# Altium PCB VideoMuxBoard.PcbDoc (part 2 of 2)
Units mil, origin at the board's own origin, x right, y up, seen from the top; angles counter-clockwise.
Board outline 4724.41 x 4724.41 mil, 4 copper layers (Top Layer, Ground, MidLayer1, Bottom Layer); 247 components, 183 nets, 999 pads, 433 vias.
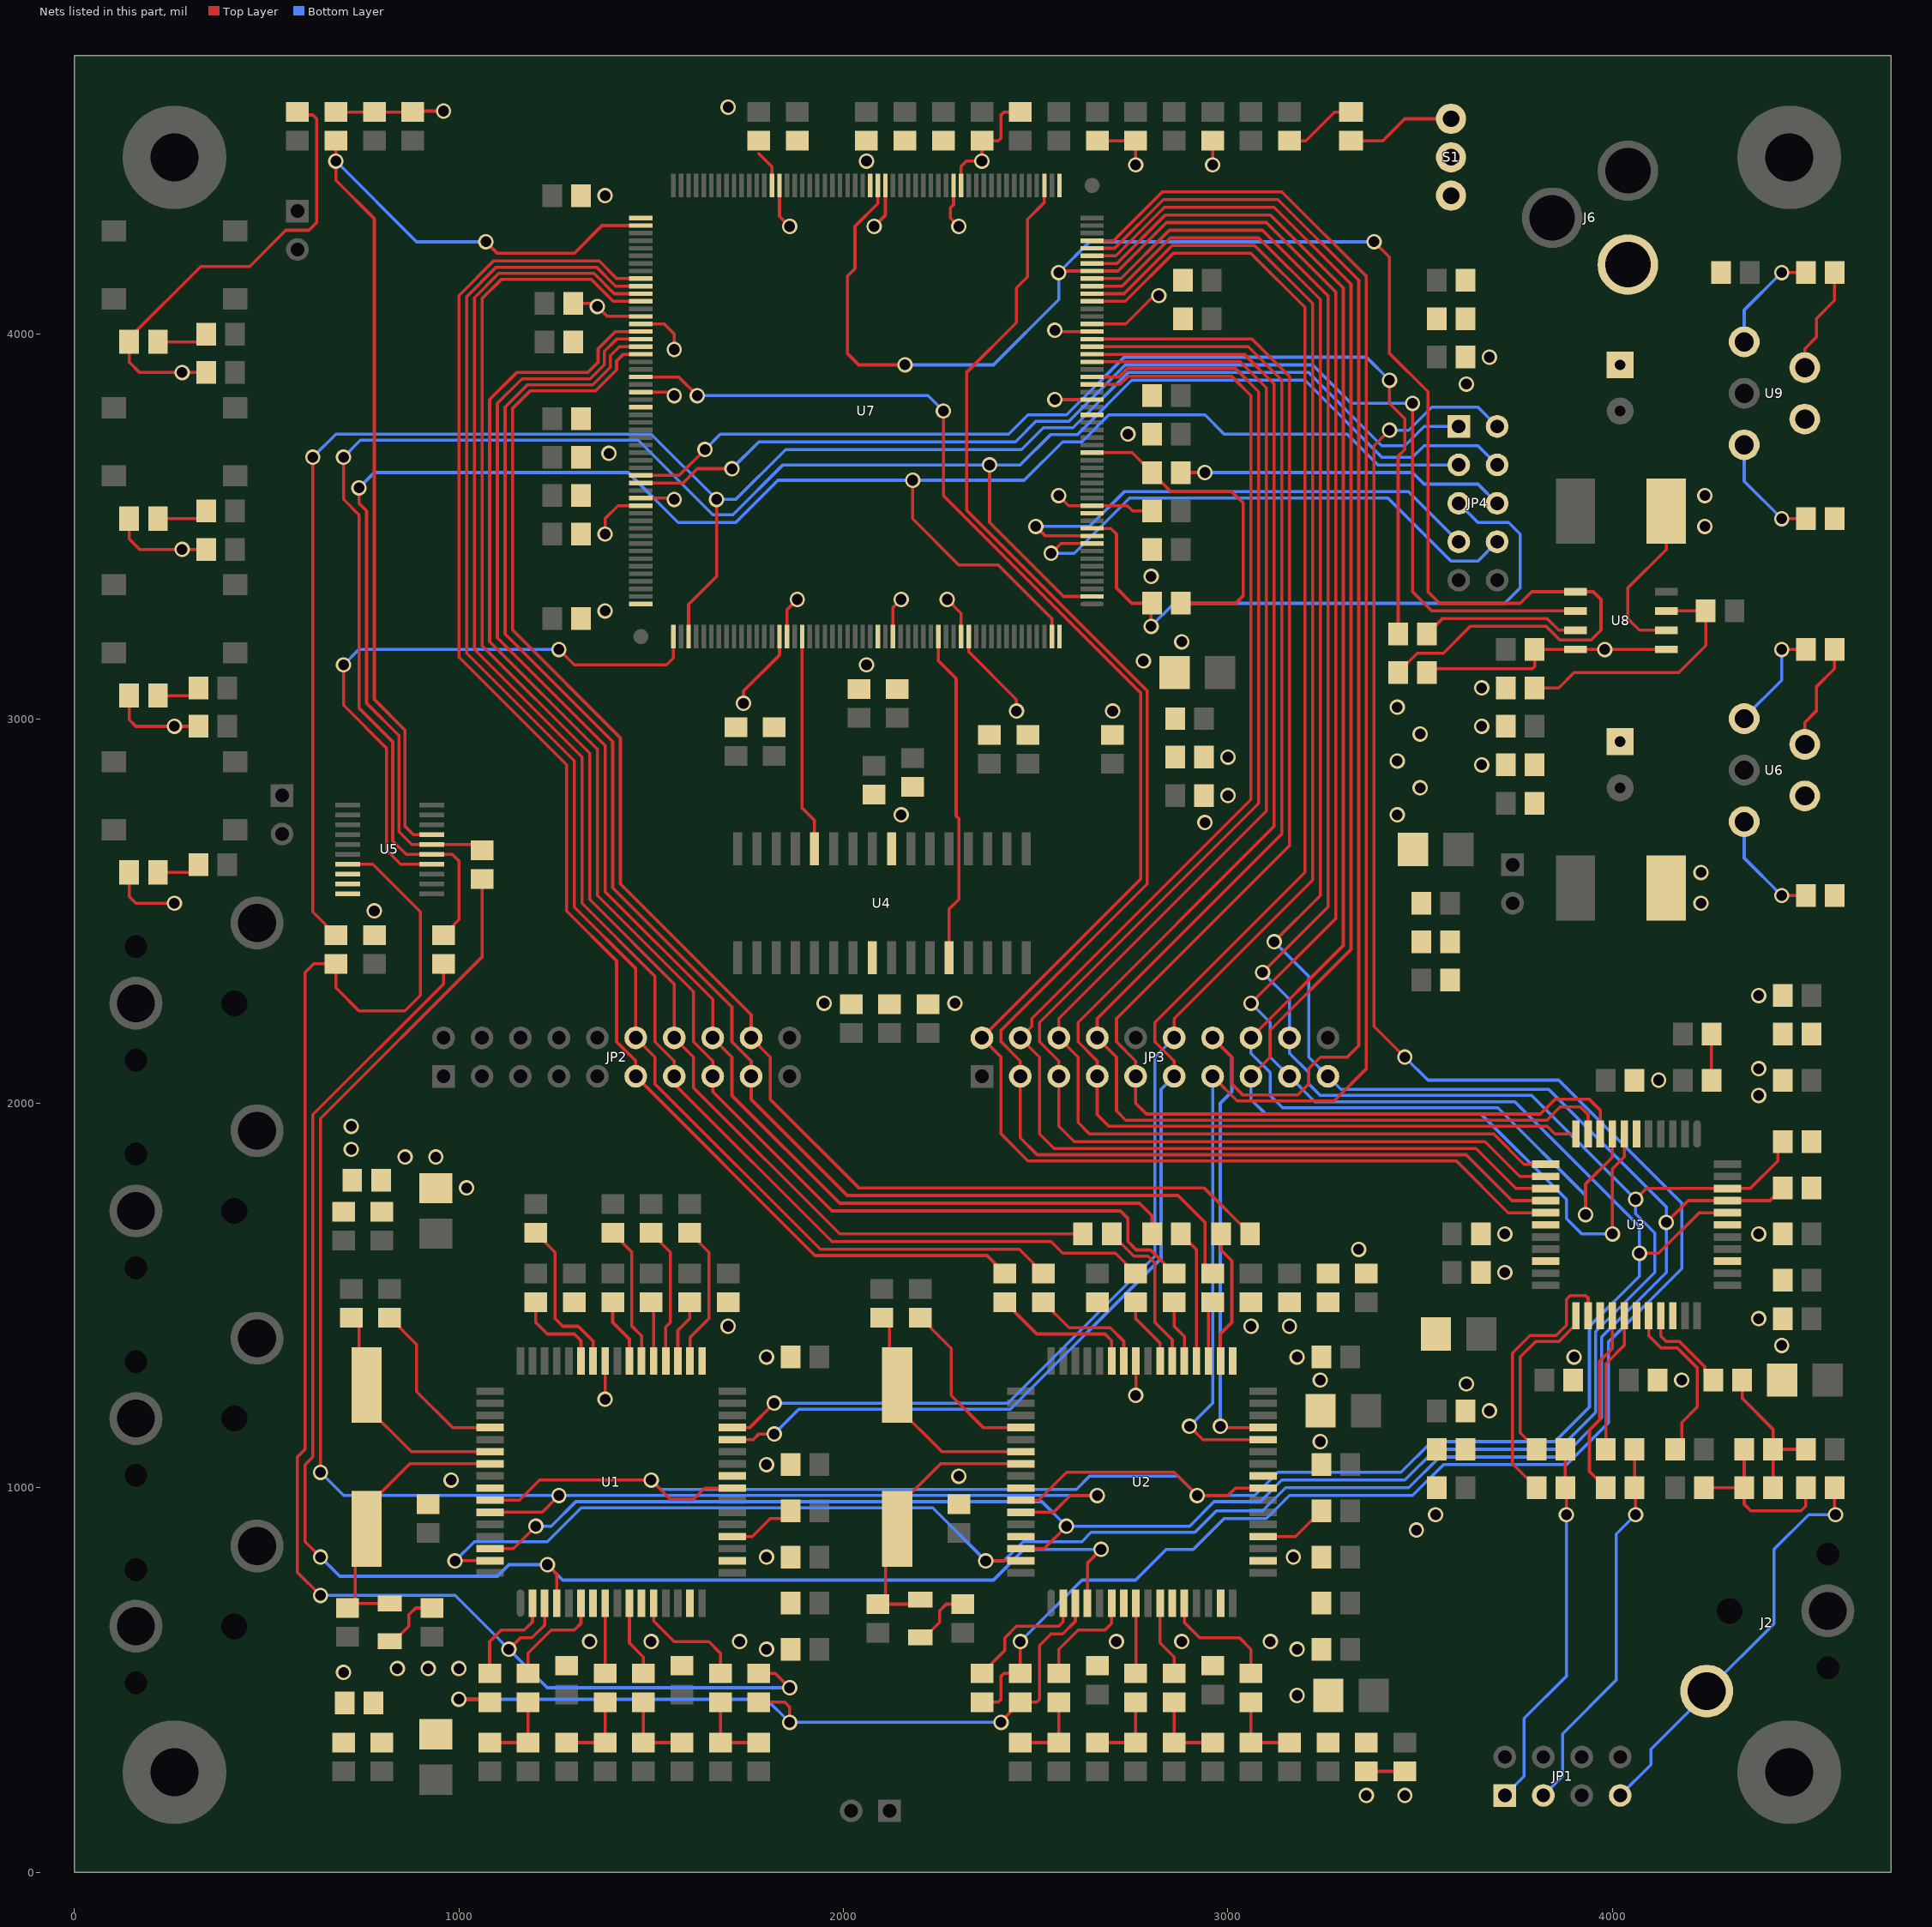
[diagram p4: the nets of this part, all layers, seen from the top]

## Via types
v1: diameter 40, hole 28, Top Layer to Bottom Layer, 433 vias

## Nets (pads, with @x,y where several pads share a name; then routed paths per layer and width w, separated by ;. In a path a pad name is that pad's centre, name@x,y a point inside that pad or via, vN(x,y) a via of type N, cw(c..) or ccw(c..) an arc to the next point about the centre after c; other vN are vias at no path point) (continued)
MPB0: JP2.11 R35.1 U7.113 | length 3922.4
  Top Layer w8: U7.113@1473.36,4144.46 1410,4144.46 1364.46,4190 1090,4190 1000,4100 1000,3160 1280,2880 1280,2500 1410,2370 1410,2160 1460,2110 JP2.11@1460,2070 1926,1604 2373.4,1604 R35.1@2420,1557.4
MPB1: JP2.12 R36.1 U7.114 | length 3969.9
  Top Layer w8: U7.114@1473.36,4124.78 1407.06,4124.78 1357.84,4174 1096.63,4174 1020,4097.37 1020,3170 1300,2890 1300,2510 1460,2350 JP2.12@1460,2170 1510,2120 1510,2050 1940,1620 2457.4,1620 R36.1@2520,1557.4
MPB2: JP2.13 R37.1 U7.115 | length 4150.9
  Top Layer w8: U7.115@1473.36,4105.09 1404.12,4105.09 1351.21,4158 1103.25,4158 1040,4094.75 1040,3180 1320,2900 1320,2520 1510,2330 1510,2160 1560,2110 JP2.13@1560,2070 ; JP2.13@1565.25,2070 JP2.13@1560,2070 ; R37.1@2760,1557.4 2707.4,1610 2570,1610 2540,1640 1970,1640 1560,2050 JP2.13@1560,2070
MPB3: JP2.14 R44.1 U7.116 | length 3907.4
  Top Layer w8: U7.116@1473.36,4085.41 1401.17,4085.41 1344.58,4142 1109.88,4142 1060,4092.12 1060,3190 1340,2910 1340,2530 1560,2310 JP2.14@1560,2170 1610,2120 1610,2040 1990,1660 R44.1@2622.6,1660
MPB4: JP2.15 R38.1 U7.120 | length 3958
  Top Layer w8: U7.120@1473.36,4006.67 1406.67,4006.67 1362,3962 1362,3927.25 1334.75,3900 1150,3900 1080,3830 1080,3200 1360,2920 1360,2540 1610,2290 1610,2160 1660,2110 JP2.15@1660,2070 1660,2030 1970,1720 2720,1720 2740,1700 2740,1640.03 2761.56,1618.47 2798.93,1618.47 R38.1@2860,1557.4
MPB5: JP2.16 R45.1 U7.121 | length 3784.8
  Top Layer w8: U7.121@1473.36,3986.98 1410,3986.98 1378,3954.98 1378,3920.63 1341.37,3884 1164,3884 1100,3820 1100,3210 1380,2930 1380,2550 1660,2270 JP2.16@1660,2170 1710,2120 1710,2020 1990,1740 2770,1740 2802.6,1707.4 R45.1@2802.6,1660
MPB6: JP2.17 R39.1 U7.122 | length 3954.6
  Top Layer w8: U7.122@1473.36,3967.3 1417.3,3967.3 1394,3944 1394,3914 1348,3868 1178,3868 1120,3810 1120,3220 1400,2940 1400,2560 1710,2250 1710,2160 1760,2110 JP2.17@1760,2070 1760,2010 2010,1760 2870,1760 2940,1690 2940,1577.4 R39.1@2960,1557.4
MPB7: JP2.18 R46.1 U7.123 | length 3872.4
  Top Layer w8: 1354.63,3853.44 1354.63,3852 1184.63,3852 1140,3807.37 1140,3230 1420,2950 1420,2570 1760,2230 JP2.18@1760,2170 1810,2120 1810,2010 2040,1780 2937.4,1780 R46.1@3057.4,1660 ; 1355.35,3852.72 1410,3907.37 1410,3930 1427.61,3947.61 U7.123@1473.36,3947.61
MPOUT0: JP3.2 U3.16 U7.126 | length 4609.1
  Top Layer w8: U7.126@1473.36,3888.56 1571.44,3888.56 v1(1620,3840) ; v1(2260,3800) 2260,3580 2773.5,3066.5 2773.5,2583.5 JP3.2@2360,2170 2410,2120 2410,1920 2480,1850 3594.14,1850 3728.87,1715.28 U3.16@3826.3,1715.27
  Bottom Layer w8: v1(1620,3840) 2220,3840 v1(2260,3800)
MPOUT1: JP3.3 U3.15 U7.55 | length 4367.2
  Top Layer w8: U7.55@2522.57,4386.59 2522.58,4342.58 2478.76,4298.76 2478.76,4148.76 2450,4120 2450,4030 2320,3900 2320,3542.63 2790,3072.63 2790,2570 2410,2190 2410,2160 2460,2110 JP3.3@2460,2070 2460,1910 2504,1866 3619.64,1866 3738.87,1746.77 U3.15@3826.3,1746.77
MPOUT2: JP3.4 U3.14 U7.30 | length 4007.1
  Top Layer w8: U7.30@2646.59,3868.87 2718.87,3868.87 2740,3890 3010,3890 3060,3840 3060,2790 2490,2220 2490,2200 JP3.4@2460,2170 2510,2120 2510,1920 2548,1882 3645.14,1882 3748.87,1778.27 U3.14@3826.3,1778.27
MPOUT3: JP3.5 U3.13 U7.31 | length 3954.2
  Top Layer w8: U7.31@2646.59,3888.56 2715.93,3888.56 2737.37,3910 3020,3910 3080,3850 3080,2780 2510,2210 2510,2160 2560,2110 JP3.5@2560,2070 2560,1940 2600,1900 3668.63,1900 3758.87,1809.76 U3.13@3826.3,1809.76
MPOUT4: JP3.6 U3.12 U7.33 | length 3897.3
  Top Layer w8: U7.33@2646.59,3927.93 3032.07,3927.93 3100,3860 3100,2760 2560,2220 JP3.6@2560,2170 2610,2120 2610,1950 2640,1920 3691.26,1920 3770,1841.26 U3.12@3826.3,1841.26
MPOUT5: JP3.7 U3.11 U7.34 | length 3903.3
  Top Layer w8: U7.34@2646.59,3947.61 3042.39,3947.61 3120,3870 3120,2720 2610,2210 2610,2160 2660,2110 JP3.7@2660,2070 2660,1970 2690,1940 3830,1940 3850,1920 U3.11@3905.04,1920
MPOUT6: JP3.8 U3.10 U7.35 | length 3957.9
  Top Layer w8: U7.35@2646.59,3967.3 3052.7,3967.3 3140,3880 3140,2700 2660,2220 JP3.8@2660,2170 2710,2120 2710,1980 2734,1956 3829.48,1956 3863.48,1990 3916.54,1990 3936.54,1970 U3.10@3936.53,1920
MPOUT7: JP3.9 U3.9 U7.36 | length 3959.6
  Top Layer w8: U7.36@2646.59,3986.98 3063.02,3986.98 3160,3890 3160,2670 2710,2220 2710,2160 2760,2110 JP3.9@2760,2070 2760,2000 2788,1972 3812,1972 3850,2010 3940,2010 3968.03,1981.97 U3.9@3968.03,1920
NetC3_1: C3.1 R9.2 R11.2 | length 205.2
  Top Layer w8: R9.2@2460,337.4 R11.2@2560,337.4 C3.1@2560,442.6
NetC3_2: C3.2 U2.6 | length 280.5
  Top Layer w8: C3.2@2560,517.4 2560,580 2610,630 2680,630 2697.48,647.48 U2.6@2697.48,700
NetC5_1: C5.1 R12.2 R13.2 | length 205.2
  Top Layer w8: R12.2@2660,337.4 R13.2@2760,337.4 C5.1@2760,442.6
NetC5_2: C5.2 U2.8 | length 182.8
  Top Layer w8: C5.2@2760,517.4 2760.47,517.88 U2.8@2760.47,700
NetC6_1: C6.1 R14.2 R15.2 | length 205.2
  Top Layer w8: C6.1@2860,442.6 R14.2@2860,337.4 R15.2@2960,337.4
NetC6_2: C6.2 U2.10 | length 197.7
  Top Layer w8: U2.10@2823.47,700 2823.46,596.54 2860,560 C6.2@2860,517.4
NetC8_1: C8.1 R16.2 R17.2 | length 205.2
  Top Layer w8: C8.1@3060,442.6 R16.2@3060,337.4 R17.2@3160,337.4
NetC8_2: C8.2 U2.12 | length 315.1
  Top Layer w8: U2.12@2886.46,700 2886.46,650 2926.46,610 3030,610 3060,580 C8.2@3060,517.4
NetC12_1: C12.1 R1.2 R2.2 | length 205.2
  Top Layer w8: R1.2@1080,337.4 R2.2@1180,337.4 C12.1@1180,442.6
NetC12_2: C12.2 U1.6 | length 274.7
  Top Layer w8: C12.2@1180,517.4 1180,570 1240,630 1300,630 1317.48,647.48 U1.6@1317.48,700
NetC14_1: C14.1 R3.2 R4.2 | length 205.2
  Top Layer w8: R3.2@1280,337.4 R4.2@1380,337.4 C14.1@1380,442.6
NetC14_2: C14.2 U1.8 | length 182.1
  Top Layer w8: C14.2@1380.47,517.88 U1.8@1380.47,700
NetC15_1: C15.1 R5.2 R6.2 | length 205.2
  Top Layer w8: C15.1@1480,442.6 R5.2@1480,337.4 R6.2@1580,337.4
NetC15_2: C15.2 U1.10 | length 197.7
  Top Layer w8: U1.10@1443.47,700 1443.46,596.54 1480,560 C15.2@1480,517.4
NetC17_1: C17.1 R7.2 R8.2 | length 205.2
  Top Layer w8: C17.1@1680,442.6 R7.2@1680,337.4 R8.2@1780,337.4
NetC17_2: C17.2 U1.12 | length 307.2
  Top Layer w8: U1.12@1506.46,700 1506.46,653.54 1560,600 1650,600 1680,570 C17.2@1680,517.4
NetC20_2: C20.2 L4.2 U2.55 X2.1 | length 755.9
  Top Layer w8: L4.2@2200,709.21 2188.19,697.4 C20.2@2090,697.4 2110,717.4 2110,862.99 X2.1@2140,892.99 2140,950 2252.2,1062.2 U2.55@2461.26,1062.2
NetC21_2: C21.2 L4.1 | length 163.5
  Top Layer w8: L4.1@2200,610.79 2210.79,610.79 2250,650 2250,680 2267.4,697.4 C21.2@2310,697.4
NetC22_2: C22.2 L3.2 U1.55 X1.1 | length 749.2
  Top Layer w8: C22.2@710,687.4 C22.2@721.81,699.21 ; L3.2@820,699.21 C22.2@721.81,699.21 ; U1.55@1081.26,1062.2 872.2,1062.2 760,950 X1.1@760,892.99 730,862.99 730,707.4 C22.2@721.81,699.21
NetC23_2: C23.2 L3.1 | length 163.5
  Top Layer w8: L3.1@820,600.79 830.79,600.79 870,640 870,670 887.4,687.4 C23.2@930,687.4
NetC33_1: C33.1 C34.2 L5.1 L7.2 | length 467.6
  Top Layer w8: C33.1@4237.4,1000 C34.2@4342.6,1000 ; L7.2@4342.6,1100 C34.2@4342.6,1000 ; L5.1@4502.6,1000 4502.6,952.6 4490,940 4360,940 4342.6,957.4 C34.2@4342.6,1000
NetC42_1: C42.1 U1.54 X1.2 | length 618.6
  Top Layer w8: C42.1@720,1442.6 740,1422.6 740,1287.01 X1.2@760,1267.01 760,1210 876.3,1093.7 U1.54@1081.26,1093.7
NetC49_1: C49.1 U2.54 X2.2 | length 618.6
  Top Layer w8: C49.1@2100,1442.6 2120,1422.6 2120,1287.01 X2.2@2140,1267.01 2140,1210 2256.3,1093.7 U2.54@2461.26,1093.7
NetC67_1: C67.1 R49.2 | length 120
  Top Layer w8: R49.2@4257.4,2060 C67.1@4257.4,2180
NetC79_1: C79.1 C80.1 L13.2 R60.2 U6.2 | length 279
  Top Layer w8: U6.2@4500,2933.07 4500,2990 4530,3020 4530,3082.6 4577.4,3130 R60.2@4577.4,3180
NetC96_1: C96.1 C106.1 L14.2 R69.2 U9.2 | length 279
  Top Layer w8: U9.2@4500,3913.07 4500,3962 4530,3992 4530,4040 4577.4,4087.4 R69.2@4577.4,4160
NetJ2_1: J2.1 JP1.7 L5.2 | length 1070.4
  Top Layer w8: v1@4577.4,932.6 L5.2@4577.4,1000
  Bottom Layer w8: JP1.7@4020,200 4100,280 4100,320 4245.04,465.04 J2.1@4245.04,471.34 4420,646.3 4420,840 4510,930 v1(4580,930)
NetJP4_6: JP4.6 R66.2 | length 855.7
  Top Layer w8: R66.2@2877.4,3640 v1(2940,3640)
  Bottom Layer w8: v1(2940,3640) 3480,3640 3510,3610 3650,3610 JP4.6@3700,3560
NetLED1_2: LED1.2 R53.1 | length 113.5
  Top Layer w8: LED1.2@217.4,2600 302.6,2600 R53.1@322.6,2620
NetLED2_2: LED2.2 R56.1 | length 113.5
  Top Layer w8: LED2.2@217.4,3060 302.6,3060 R56.1@322.6,3080
NetLED3_2: LED3.2 R65.1 | length 133.5
  Top Layer w8: LED3.2@217.4,3520 322.6,3520 R65.1@342.6,3540
NetLED4_2: LED4.2 R68.1 | length 133.5
  Top Layer w8: LED4.2@217.4,3980 322.6,3980 R68.1@342.6,4000
NetLED5_2: LED5.2 R77.1 | length 191
  Top Layer w8: R77.1@3160,4502.6 3202.6,4502.6 3277.4,4577.4 LED5.2@3320,4577.4
NetR18_2: R19.2 U2.2 | length 334.6
  Top Layer w8: R19.2@2360,517.4 2420,577.4 2420,610 2450,640 2560,640 2571.5,651.5 U2.2@2571.5,700
NetR19_2: R18.2 U1.2 | length 263.9
  Top Layer w8: R18.2@1080,517.4 1080,600 1110,630 1170,630 1191.5,651.5 U1.2@1191.5,700
NetR21_2: R21.2 U1.20 | length 179.1
  Top Layer w8: U1.20@1711.18,873.23 1763.23,873.23 1810,920 1842.6,920 R21.2@1862.6,940
NetR22_2: R22.2 U2.20 | length 179.1
  Top Layer w8: U2.20@3091.18,873.23 3175.83,873.23 R22.2@3242.6,940
NetR23_1: R23.1 U3.24 | length 722.8
  Top Layer w8: R23.1@3802.6,1000 3740,1062.6 3740,1350 3785.87,1395.87 3853.42,1395.87 3880,1422.45 3880,1490 3890,1500 3930,1500 3936.53,1493.47 U3.24@3936.53,1447.56
NetR24_1: R24.1 U3.26 | length 489.9
  Top Layer w8: R24.1@3982.6,1000 3940,1042.6 3940,1150 3966.72,1176.72 3966.72,1329.17 3999.53,1361.98 U3.26@3999.53,1447.56
NetR25_1: R25.1 U3.23 | length 460.4
  Top Layer w8: R25.1@3802.6,1100 3760,1142.6 3760,1340 3800,1380 3860,1380 3905.04,1425.04 U3.23@3905.04,1447.56
NetR26_1: R26.1 U3.27 | length 367.6
  Top Layer w8: R26.1@3982.6,1100 3982.6,1322.6 4031.02,1371.02 U3.27@4031.02,1447.56
NetR27_1: R27.1 U3.29 | length 448.4
  Top Layer w8: U3.29@4094.02,1447.56 4094.02,1395.98 4125.87,1364.13 4168.32,1364.13 4220,1312.45 4220,1210 4180,1170 4180,1117.4 R27.1@4162.6,1100
NetR28_1: R28.1 U3.30 | length 244.8
  Top Layer w8: U3.30@4125.51,1447.56 4125.51,1394.49 4140,1380 4174.9,1380 4240,1314.9 4240,1302.6 R28.1@4262.6,1280
NetR29_2: R29.2 U1.52 | length 451.5
  Top Layer w8: R29.2@820,1442.6 890,1372.6 890,1250 983.31,1156.69 U1.52@1081.26,1156.69
NetR30_2: R30.2 U1.43 | length 242.3
  Top Layer w8: R30.2@1200,1482.6 1200,1430 1230,1400 1300,1400 1317.48,1382.52 U1.43@1317.48,1329.92
NetR31_2: R31.2 U1.39 | length 170.7
  Top Layer w8: R31.2@1400,1482.6 1400,1430 1443.46,1386.54 U1.39@1443.47,1329.92
NetR32_2: R32.2 U1.37 | length 155.4
  Top Layer w8: R32.2@1500,1482.6 1506.46,1476.14 U1.37@1506.46,1329.92
NetR33_2: R33.2 U1.35 | length 165.3
  Top Layer w8: U1.35@1569.45,1329.92 1569.45,1409.45 1600,1440 R33.2@1600,1482.6
NetR34_2: R34.2 U2.52 | length 451.5
  Top Layer w8: R34.2@2200,1442.6 2280,1362.6 2280,1240 2363.31,1156.69 U2.52@2461.26,1156.69
NetR35_2: R35.2 U2.43 | length 371.5
  Top Layer w8: R35.2@2420,1482.6 2502.6,1400 2680,1400 2697.48,1382.52 U2.43@2697.48,1329.92
NetR36_2: R36.2 U2.42 | length 302.2
  Top Layer w8: R36.2@2520,1482.6 2586.6,1416 2694,1416 2728.98,1381.02 U2.42@2728.98,1329.92
NetR37_2: R37.2 U2.39 | length 179
  Top Layer w8: R37.2@2760,1482.6 2760,1440 2823.46,1376.54 U2.39@2823.47,1329.92
NetR38_2: R38.2 U2.37 | length 163.6
  Top Layer w8: R38.2@2860,1482.6 2860,1420 2886.46,1393.54 U2.37@2886.46,1329.92
NetR39_2: R39.2 U2.35 | length 157
  Top Layer w8: U2.35@2949.45,1329.92 2949.45,1472.05 R39.2@2960,1482.6
NetR40_2: R40.2 U1.42 | length 417.8
  Top Layer w8: R40.2@1200,1662.6 1250,1612.6 1250,1440 1270,1420 1310,1420 1348.98,1381.02 U1.42@1348.98,1329.92
NetR41_2: R41.2 U1.38 | length 363.7
  Top Layer w8: R41.2@1400,1662.6 1450,1612.6 1450,1420 1474.96,1395.04 U1.38@1474.96,1329.92
NetR42_2: R42.2 U1.36 | length 358.4
  Top Layer w8: R42.2@1500,1662.6 1550,1612.6 1550,1430 1537.95,1417.95 U1.36@1537.95,1329.92
NetR43_2: R43.2 U1.34 | length 373.7
  Top Layer w8: R43.2@1600,1662.6 1650,1612.6 1650,1440 1600.95,1390.94 U1.34@1600.95,1329.92
NetR44_2: R44.2 U2.38 | length 417.2
  Top Layer w8: R44.2@2697.4,1660 2754.93,1602.47 2792.3,1602.47 2810,1584.77 2810,1430 2854.96,1385.04 U2.38@2854.96,1329.92
NetR45_2: R45.2 U2.36 | length 346.9
  Top Layer w8: R45.2@2877.4,1660 2917.95,1619.45 U2.36@2917.95,1329.92
NetR46_2: R46.2 U2.34 | length 353.5
  Top Layer w8: U2.34@2980.94,1329.92 2980.94,1400.94 3010,1430 3010,1590 2982.6,1617.4 R46.2@2982.6,1660
NetR52_1: R52.1 U6.5 | length 295.3
  Top Layer w8: v1(4440,2540) R52.1@4502.6,2540
  Bottom Layer w8: U6.5@4342.52,2732.28 4342.52,2637.48 v1(4440,2540)
NetR58_2: R58.2 R62.1 U8.3 | length 683.4
  Top Layer w8: R58.2@3797.4,3080 3860,3080 3900,3120 4172.6,3120 4242.6,3190 R62.1@4242.6,3280 U8.3@4140,3280
NetR59_2: R59.2 U8.7 | length 415.4
  Top Layer w8: R59.2@3517.4,3220 3557.4,3260 3830,3260 3860,3230 U8.7@3903.78,3230
NetR60_1: R60.1 U6.1 | length 286.5
  Top Layer w8: v1(4440,3180) R60.1@4502.6,3180
  Bottom Layer w8: U6.1@4340,3000 4341.26,3001.26 U6.1@4342.52,3002.52 ; U6.1@4342.52,3000 U6.1@4342.52,3002.52 ; v1(4440,3180) 4440,3100 U6.1@4342.52,3002.52
NetR64_1: R64.1 U9.5 | length 295.3
  Top Layer w8: v1(4440,3520) R64.1@4502.6,3520
  Bottom Layer w8: U9.5@4342.52,3712.28 4342.52,3617.48 v1(4440,3520)
NetR69_1: R69.1 U9.1 | length 283
  Top Layer w8: v1(4440,4160) R69.1@4502.6,4160
  Bottom Layer w8: U9.1@4342.52,3980 4342.52,4062.52 v1(4440,4160)
OEBAR: U4.28 U7.174 | length 565
  Top Layer w8: U7.174@1892.65,3213.36 1892.65,2767.35 1925,2735 U4.28@1925,2661.73
POS1_8V: C78.1 C92.1 L12.1 R64.2 U8.2 U9.4 | length 433.8
  Top Layer w8: U8.2@4140,3230 4070,3230 4040,3260 4040,3340 4140,3440 C92.1@4140,3540
  other v1: 2940,2730 3000,2800 3000,2900 4240,3500 4240,3580
POS3_3V: C10.1 C11.1 C32.1 C53.1 C56.1 C68.1 C69.1 C71.1 C88.1 L1.1 L2.1 L6.1 L8.1 L9.1 L10.1 L11.1 LED1.1 LED2.1 LED3.1 LED4.1 R52.2 R55.1 R57.2 R63.1 R67.1 R78.1 U6.4 U8.1 U8.8 | length 2687.4
  Top Layer w8: LED1.1@142.6,2600 142.6,2537.4 160,2520 v1(260,2520) ; LED2.1@142.6,3060 142.6,2997.4 160,2980 v1(260,2980) R55.1@322.6,2980 ; LED3.1@142.6,3520 142.6,3467.4 170,3440 v1(280,3440) R63.1@342.6,3440 ; R67.1@342.6,3900 v1(280,3900) 170,3900 142.6,3927.4 LED4.1@142.6,3980 142.6,3990 328.6,4176 456,4176 550,4270 610,4270 630,4290 630,4560 620,4570 587.4,4570 R78.1@580,4577.4 ; L1.1@3360,262.6 C10.1@3460,262.6 ; R57.2@3517.4,3120 3527.4,3130 3792,3130 3797.4,3135.4 C88.1@3797.4,3180 U8.8@3903.78,3180 v1(3980,3180) U8.1@4140,3180
  other v1: 3360,200 3460,200 700,520 3490,890 3540,930 3340,1620 720,1880 720,1940 4380,2280 4230,2520 4230,2600
POS5V: C86.1 C101.1 L13.1 L14.1 LED5.1 R58.1 S1.3 | length 283.8
  Top Layer w8: LED5.1@3320,4502.6 3402.6,4502.6 3460,4560 S1.3@3580,4560
  other v1: 3660,2880 3660,2980 3660,3080 3620,3870 3680,3940
PROGRAM: R70.2 U5.7 U7.106 | length 2858.1
  Top Layer w8: R70.2@680,4502.6 v1(680,4450) 680,4400 780,4300 780,3050 860,2970 860,2720 881.61,2698.39 U5.7@929.25,2698.39 ; v1(1070,4240) 1100,4210 1300,4210 1372.26,4282.26 U7.106@1473.36,4282.26
  Bottom Layer w8: v1(680,4450) 890,4240 v1(1070,4240)
PWR_IN: C104.1 J6.1 S1.1 S1.2 | length 29.2
  Top Layer w40: J6.1@4040,4180.63 J6.1@4060.63,4160
PWRGOOD: U7.140 U8.6 | length 3109.7
  Top Layer w8: U7.140@1473.36,3612.97 1582.97,3612.97 1620,3650 v1(1710,3650) ; v1(3480,3820) 3480,3330 3530,3280 U8.6@3903.78,3280
  Bottom Layer w8: v1(1710,3650) 1780,3720 2447.18,3720 2500,3772.82 2585.45,3772.82 2732.63,3920 3220,3920 3320,3820 v1(3480,3820)
RCV1: JP3.15 U3.7 U7.47 | length 4423.5
  Top Layer w8: U7.47@2646.59,4203.52 2708.26,4203.52 2834.74,4330 3120,4330 3320,4130 3320,2400 3110,2190 3110,2120 JP3.15@3060,2070 ; v1(4000,1660) 4000,1830 4031.02,1861.02 U3.7@4031.02,1920
  Bottom Layer w8: JP3.15@3060,2070 3060,2010 3098,1972 3658,1972 3880,1750 3880,1700 3920,1660 v1(4000,1660)
RCV2: JP3.16 U3.8 U7.46 | length 4221
  Top Layer w8: U7.46@2646.59,4183.83 2711.21,4183.83 2837.37,4310 3110,4310 3300,4120 3300,2410 JP3.16@3060,2170 ; v1(3930,1710) 3930,1790 3999.53,1859.53 U3.8@3999.53,1920
  Bottom Layer w8: JP3.16@3060,2170 3060,2130 3110,2080 3110,2020 3142,1988 3702,1988 3930,1760 v1(3930,1710)
RESETBAR: JP3.17 R57.1 U1.24 U1.58 U2.24 U2.58 U3.40 U7.45 U7.77 U8.5 | length 13004.3
  Top Layer w8: U1.58@1081.26,967.72 1157.72,967.72 1210,1020 v1(1500,1020) 1550,970 1610,970 1639.21,999.21 U1.24@1711.18,999.21 ; U7.77@2089.5,4386.59 2089.5,4339.5 2030,4280 2030,4170 2010,4150 2010,3950 2040,3920 v1(2160,3920) ; U2.58@2461.26,967.72 2507.72,967.72 2580,1040 2860,1040 v1(2920,980) 3000,980 3019.21,999.21 U2.24@3091.18,999.21 ; v1(2560,4160) 2564.15,4164.15 U7.45@2646.59,4164.15 2714.15,4164.15 2840,4290 3100,4290 3280,4110 3280,2480 v1(3060,2260) ; v1(3380,4240) 3420,4200 3420,3950 3520,3850 3520,3330 3550,3300 3760,3300 3790,3330 U8.5@3903.78,3330 3950,3330 3970,3310 3970,3230 3945,3205 3862.55,3205 3827.55,3240 3630,3240 3560,3170 3492.6,3170 R57.1@3442.6,3120 ; v1(4070,1610) 4120,1610 4225.27,1715.27 U3.40@4298.74,1715.27
  Bottom Layer w8: v1(1500,1020) 1524,996 2606,996 2640,1030 2870,1030 v1(2920,980) 3070,980 3130,1040 3450,1040 3530,1120 3850,1120 3940,1210 3940,1420 4070,1550 v1(4070,1610) 4070,1680 3746,2004 3226,2004 JP3.17@3160,2070 3110,2120 3110,2210 v1(3060,2260) ; v1(2160,3920) 2390,3920 2560,4090 v1(2560,4160) 2640,4240 v1(3380,4240)
RTSA0: JP3.11 U1.28 U7.41 | length 4643.2
  Top Layer w8: U1.28@1711.18,1125.2 1765.2,1125.2 1780,1140 v1(1820,1140) ; U7.41@2646.59,4085.41 2732.78,4085.41 2857.37,4210 3060,4210 3200,4070 3200,2600 2810,2210 2810,2160 2860,2110 JP3.11@2860,2070
  Bottom Layer w8: v1(1820,1140) 1884,1204 2434,1204 2826,1596 2826,2036 JP3.11@2860,2070
RTSA1: JP3.12 U1.29 U7.42 | length 4618
  Top Layer w8: U1.29@1711.18,1156.69 1756.69,1156.69 v1(1820,1220) ; U7.42@2646.59,4105.09 2729.84,4105.09 2854.75,4230 3070,4230 3220,4080 3220,2580 2860,2220 JP3.12@2860,2170
  Bottom Layer w8: v1(1820,1220) 2427.37,1220 2810,1602.63 2810,2120 JP3.12@2860,2170
RTSB0: JP3.13 U2.28 U7.49 | length 4518.9
  Top Layer w8: U7.49@2646.59,4242.89 2702.38,4242.89 2829.49,4370 3140,4370 3360,4150 3360,2090 3276,2006 3024,2006 JP3.13@2960,2070 ; v1(2900,1160) 2934.8,1125.2 U2.28@3091.18,1125.2
  Bottom Layer w8: v1(2900,1160) 2960,1220 JP3.13@2960,2070
RTSB1: JP3.14 U2.29 U7.48 | length 4537.4
  Top Layer w8: U7.48@2646.59,4223.2 2705.32,4223.2 2832.12,4350 3130,4350 3340,4140 3340,2150 3310,2120 3240,2120 3210,2090 3210,2050 3182,2022 3038,2022 3010,2050 3010,2120 JP3.14@2960,2170 ; v1(2980,1160) 2983.31,1156.69 U2.29@3091.18,1156.69
  Bottom Layer w8: JP3.14@2960,2170 3010,2120 3010,2030 2980,2000 v1(2980,1160)
SCL: JP3.19 R47.1 U1.63 U2.63 U3.41 U7.43 | length 8250.7
  Top Layer w8: v1(990,810) 990.24,810.24 U1.63@1081.26,810.24 ; v1(2370,810) 2370.24,810.24 U2.63@2461.26,810.24 ; U7.43@2646.59,4124.78 2724.78,4124.78 2850,4250 3080,4250 3240,4090 3240,2540 v1(3120,2420) ; v1(4140,1690) 4196.77,1746.77 U3.41@4298.74,1746.77 4409.37,1746.77 R47.1@4442.6,1780
  Bottom Layer w8: v1(990,810) 1040,860 1230,860 1318,948 2232,948 v1(2370,810) 2417.37,810 2467.37,860 2620,860 2644,884 2914,884 2970,940 3090,940 3150,1000 3470,1000 3550,1080 3870,1080 3972,1182 3972,1392 4140,1560 v1(4140,1690) 4140,1730 3834,2036 3294,2036 JP3.19@3260,2070 3210,2120 3210,2330 v1(3120,2420)
SDA: JP3.18 R48.1 U1.62 U2.62 U3.42 U7.44 | length 8202.7
  Top Layer w8: U1.62@1081.26,841.73 1141.73,841.73 v1(1200,900) ; U2.62@2461.26,841.73 2521.73,841.73 v1(2580,900) ; U7.44@2646.59,4144.46 2721.84,4144.46 2847.37,4270 3090,4270 3260,4100 3260,2510 v1(3090,2340) ; v1(4060,1750) 4088.27,1778.27 U3.42@4298.74,1778.27 4358.27,1778.27 4430,1850 4430,1887.4 R48.1@4442.6,1900
  Bottom Layer w8: v1(1200,900) 1240,900 1304,964 2516,964 v1(2580,900) 2900,900 2964,964 3084,964 3140,1020 3460,1020 3540,1100 3860,1100 3956,1196 3956,1406 4110,1560 4110,1662.63 4060,1712.63 v1(4060,1750) 3790,2020 3240,2020 3210,2050 3210,2080 3160,2130 JP3.18@3160,2170 3160,2270 v1(3090,2340)
TCK: R54.2 U1.59 U2.59 | length 4175.2
  Top Layer w8: v1(640,1040) 640,1960 1060,2380 R54.2@1060,2582.6 ; U1.59@1081.26,936.22 1216.22,936.22 v1(1260,980) ; U2.59@2461.26,936.22 2546.22,936.22 2590,980 v1(2660,980)
  Bottom Layer w8: v1(640,1040) 700,980 v1(2660,980)
TCK_HARD: JP4.3 R54.1 U5.6 U7.207 | length 4890
  Top Layer w8: v1(740,3600) 740,3560 760,3540 760,3040 844,2956 844,2706 877.2,2672.8 U5.6@929.25,2672.8 1044.61,2672.8 R54.1@1060,2657.4 ; v1(2180,3620) 2180,3520 2300.65,3399.35 2402.91,3399.35 2542.26,3260 U7.207@2542.26,3213.36
  Bottom Layer w8: v1(740,3600) 780,3640 1440,3640 1570,3510 1720,3510 1830,3620 2470,3620 2570,3720 2620,3720 2690,3790 2940,3790 2990,3740 3310,3740 3390,3660 JP4.3@3600,3660
TCK_SOFT: JP4.7 U7.10 | length 1348
  Top Layer w8: v1(2500,3500) 2524.83,3475.17 U7.10@2646.59,3475.17
  Bottom Layer w8: v1(2500,3500) 2640,3500 2730,3590 3470,3590 JP4.7@3600,3460
TDI_B: R10.1 R18.1 R20.2 U2.3 | length 2075.6
  Top Layer w8: v1(1000,450) 1072.6,450 R18.1@1080,442.6 ; R20.2@1780,442.6 1847.4,442.6 1860,430 v1(1860,390) ; v1(2410,390) 2410,392.6 R10.1@2460,442.6 2502.6,442.6 2510,450 2510,590 2540.04,620.04 2570.04,620.04 2602.99,652.99 U2.3@2602.99,700
  Bottom Layer w8: v1(1000,450) 1800,450 v1(1860,390) v1(2410,390)
TDI_HARD: JP4.1 R50.1 U7.159 | length 4965.5
  Top Layer w8: v1(620,3680) 620,2497.4 R50.1@680,2437.4 ; U7.159@1597.38,3213.36 1597.38,3297.38 1670,3370 v1(1670,3570)
  Bottom Layer w8: v1(620,3680) 680,3740 1500,3740 v1(1670,3570) 1720,3570 1850,3700 2463.18,3700 2520,3756.82 2596.82,3756.82 2740,3900 3210,3900 3400,3710 3460,3710 3510,3760 JP4.1@3600,3760
TDI_SOFT: JP4.5 R61.1 U7.11 | length 1714.4
  Top Layer w8: U7.11@2646.59,3494.86 2695.14,3494.86 2710,3480 2710,3340 2750,3300 R61.1@2802.6,3300 2800,3297.4 v1(2800,3240)
  Bottom Layer w8: v1(2800,3240) 2860,3300 3720,3300 3760,3340 3760,3480 3730,3510 3650,3510 JP4.5@3600,3560
TDO_B: JP4.2 R10.2 R19.1 | length 5546.2
  Top Layer w8: R19.1@2360,442.6 2402.6,442.6 2410,450 2410,510 2417.4,517.4 R10.2@2460,517.4 v1(2460,600) ; v1(3420,3750) 3380,3710 3380,2200 v1(3460,2120)
  Bottom Layer w8: v1(2460,600) 2620,760 2760,760 2840,840 2910,840 2990,920 3100,920 3160,980 3480,980 3560,1060 3880,1060 3990,1170 3990,1380 4180,1570 4180,1740 3860,2060 3520,2060 v1(3460,2120) ; v1(3420,3750) 3470,3750 3530,3810 3650,3810 JP4.2@3700,3760
TDO_CONTROLLER: R20.1 R50.2 U1.3 U5.17 | length 4115.6
  Top Layer w8: v1(640,720) 580,780 580,1080 600,1100 600,2340 622.6,2362.6 R50.2@680,2362.6 680,2300 740,2240 860,2240 900,2280 900,2497.37 775.76,2621.61 U5.17@710.75,2621.61 ; v1(1130,580) 1160,610 1190,610 1222.99,642.99 U1.3@1222.99,700 ; R20.1@1780,517.4 1822.6,517.4 v1(1860,480)
  Bottom Layer w8: v1(640,720) 990,720 1230,480 v1(1860,480)
TDO_SOFT: R61.2 R66.1 U7.21 | length 858.8
  Top Layer w8: U7.21@2646.59,3691.71 2750.89,3691.71 R66.1@2802.6,3640 2852.6,3590 3010,3590 3040,3560 3040,3320 3020,3300 R61.2@2877.4,3300
TDO_SPARTAN: U5.4 U7.157 | length 1614.7
  Top Layer w8: v1(700,3140) 700,3035.25 812,2923.25 812,2658 848.39,2621.61 U5.4@929.25,2621.61 ; v1(1260,3180) 1300,3140 1540,3140 1558.01,3158.01 U7.157@1558.01,3213.36
  Bottom Layer w8: v1(700,3140) 740,3180 v1(1260,3180)
TMS: R51.2 U1.4 U2.4 | length 4086
  Top Layer w8: v1(640,820) 600,860 600,1060 620,1080 620,1970 960,2310 R51.2@960,2362.6 ; v1(1230,800) 1254.49,775.51 U1.4@1254.49,700 ; U2.4@2634.49,700 2634.49,804.49 v1(2670,840)
  Bottom Layer w8: v1(640,820) 690,770 1100,770 1130,800 v1(1230,800) 1270,760 2390,760 2470,840 v1(2670,840)
TMS_HARD: JP4.4 R51.1 U5.5 U7.2 | length 5309.5
  Top Layer w8: v1(700,3680) 700,3570 740,3530 740,3027.88 828,2939.88 828,2682 862.8,2647.2 982.8,2647.2 1000,2630 1000,2477.4 R51.1@960,2437.4 ; v1(2380,3660) 2380,3510 2572.31,3317.69 U7.2@2646.59,3317.69
  Bottom Layer w8: v1(700,3680) 744,3724 1466,3724 1660,3530 1712.63,3530 1842.63,3660 2460,3660 2538.34,3738.34 2608.34,3738.34 2621.71,3751.71 2750,3880 3200,3880 3400,3680 3480,3680 3510,3710 3650,3710 JP4.4@3700,3660
TMS_SOFT: JP4.8 U7.9 | length 1425.4
  Top Layer w8: v1(2540,3430) 2565.49,3455.49 U7.9@2646.59,3455.49
  Bottom Layer w8: v1(2540,3430) 2600,3430 2744,3574 3416,3574 3580,3410 3650,3410 JP4.8@3700,3460
VCC1_8V: C75.1 C81.2 C84.1 C85.1 C87.1 C93.1 C94.1 C97.2 C99.2 C100.1 C103.1 C110.2 C112.2 C113.1 L12.2 U7.14 U7.28 U7.37 U7.67 U7.76 U7.90 U7.119 U7.128 U7.142 U7.172 U7.186 U7.195 | length 1450.1
  Top Layer w8: U7.142@1473.36,3573.6 1556.4,3573.6 v1(1560,3570) ; U7.128@1473.36,3849.19 1550.81,3849.19 v1(1560,3840) ; U7.119@1473.36,4026.35 1533.65,4026.35 1560,4000 v1(1560,3960) ; U7.90@1833.6,4386.59 1833.6,4306.4 v1(1860,4280) ; U7.172@1853.28,3213.36 1853.28,3283.28 v1(1880,3310) ; v1(2080,4280) 2109.19,4309.19 U7.76@2109.19,4386.59 ; U7.186@2128.87,3213.36 2128.87,3288.87 v1(2150,3310) ; v1(2270,3310) 2306.04,3273.96 U7.195@2306.04,3213.36 ; U7.67@2286.35,4386.59 2286.35,4336.35 2277.94,4327.94 2277.94,4302.06 v1(2300,4280) ; v1(2550,3830) 2550.5,3829.5 U7.28@2646.59,3829.5 ; v1(2550,4010) 2553.33,4006.67 U7.37@2646.59,4006.67 ; v1(2560,3580) 2586.09,3553.91 U7.14@2646.59,3553.91 2738.09,3553.91 2752,3540 C94.1@2802.6,3540
  other v1: 2780,3150 2880,3200
VCC3_3V: C61.1 C62.1 C63.1 C66.1 C70.1 C72.1 C73.1 C74.1 C76.1 C77.1 C82.1 C83.1 C89.1 C90.1 C91.1 C95.1 C98.1 C102.1 C105.1 C107.1 C108.1 C109.1 C111.1 C114.1 L11.2 R70.1 R71.1 R72.1 R73.1 R75.1 R80.1 U4.8 U4.24 U5.18 U5.19 U5.20 U7.13 U7.26 U7.38 U7.53 U7.66 U7.78 U7.91 U7.105 U7.118 U7.130 U7.143 U7.156 U7.171 U7.184 U7.196 U7.208 | length 1925.5
  Top Layer w8: R70.1@680,4577.4 R71.1@780,4577.4 R72.1@880,4577.4 882.6,4580 v1(960,4580) ; C102.1@1297.4,4080 1352,4080 v1(1360,4072) 1385.96,4046.04 U7.118@1473.36,4046.04 ; v1(1380,3480) 1380,3520 1413.91,3553.91 U7.143@1473.36,3553.91 ; v1(1740,3040) 1740,3071.61 1833.6,3165.21 U7.171@1833.6,3213.36 ; 1780,4469.01 1813.91,4435.09 U7.91@1813.91,4386.59 ; U7.66@2306.04,4386.59 2306.04,4436.04 2320,4450 2354,4450 2357,4453 2360,4456 C114.1@2360,4502.6 2402.6,4502.6 2410,4510 2410,4570 2417.4,4577.4 R80.1@2460,4577.4 ; U7.196@2325.72,3213.36 2325.72,3173.81 2450,3049.53 v1(2450,3020) ; U7.38@2646.59,4026.35 2733.73,4026.35 2807.37,4100 v1(2820,4100) ; C107.1@2660,4502.6 R73.1@2760,4502.6 v1(2760,4440) ; v1(2960,4440) R75.1@2960,4502.6
  other v1: 1950,2260 2290,2260 780,2500 2150,2750 3440,2750 3500,2820 3440,2890 3500,2960 2700,3020 3440,3030 2060,3140 1380,3280 2800,3370 1390,3690 2740,3740 1380,4360 2060,4450 2360,4450 1700,4590
VDDA_A: C1.1 C2.1 C13.2 C16.2 C19.2 C25.2 L2.2 U1.7 U1.11 U1.15
  other v1: 840,530 920,530 1000,530 1800,580 1340,600 1500,600 1730,600
VDDA_B: C4.2 C7.2 C9.1 C18.1 C24.2 C26.2 L1.2 U2.7 U2.11 U2.15
  other v1: 3180,460 3180,580 2710,600 2880,600 3110,600
VDDA_E: C38.1 C39.1 C40.1 C41.1 C46.1 C54.1 L6.2 U3.25 U3.28 U3.31 U3.36
  other v1: 3680,1200 3620,1270 4180,1280 3900,1340 4440,1370 4380,1440
VDDD_A: C27.1 C29.1 C31.1 C43.1 C47.1 C48.1 C57.1 C58.1 L9.2 U1.18 U1.25 U1.33 U1.41 U1.57 | length 99.4
  Top Layer w8: v1@1380.47,1230.47 U1.41@1380.47,1329.92
  other v1: 1800,820 980,1020 1800,1060 1380,1230 1800,1340 1700,1420 1020,1780 860,1860 940,1860
VDDD_B: C28.1 C30.1 C35.1 C37.1 C44.1 C50.1 C51.1 C52.1 L8.2 U2.18 U2.25 U2.33 U2.41 U2.57 U2.61 | length 90.5
  Top Layer w8: v1(2760,1240) 2760.47,1240.47 U2.41@2760.47,1329.92 ; U2.18@3090.95,810 U2.18@3091.18,810.24
  other v1: 3170,820 2300,1030 3240,1120 3240,1280 3180,1340 3060,1420 3160,1420
VDDD_E: C45.1 C55.2 C59.2 C60.2 C64.1 C65.2 L10.2 R47.2 R48.2 U3.6 U3.17 U3.20 U3.39
  other v1: 3720,1560 3720,1660 4380,1660 4380,2020 4120,2060 4380,2090
VID_C: JP1.1 R23.2 R25.2 | length 974.8
  Top Layer w8: R23.2@3877.4,992.6 R25.2@3877.4,1100 ; R23.2@3877.4,1000 3880,997.4 v1(3880,930)
  Bottom Layer w8: JP1.1@3720,200 3770,250 3770,400 3880,510 v1(3880,930)
VID_CVBS: C34.1 C36.1 L7.1 R28.2 | length 398.3
  Top Layer w8: R28.2@4337.4,1280 4337.4,1232.6 4417.4,1152.6 C34.1@4417.4,1000 ; L7.1@4417.4,1100 C36.1@4502.6,1100
VID_Y: JP1.3 R24.2 R26.2 | length 1003.1
  Top Layer w8: R24.2@4057.4,997.4 R26.2@4057.4,1100 ; R24.2@4057.4,1000 4060,997.4 v1(4060,930)
  Bottom Layer w8: JP1.3@3820,200 3870,250 3870,360 4010,500 4010,880 v1(4060,930)
WDOG: R59.1 U7.139 | length 2782.6
  Top Layer w8: U7.139@1473.36,3632.65 1572.65,3632.65 v1(1640,3700) ; v1(3420,3880) 3420,3820 3460,3780 3460,3700 3442.6,3682.6 R59.1@3442.6,3220
  Bottom Layer w8: v1(1640,3700) 1680,3740 2430,3740 2480,3790 2580,3790 2608.9,3818.9 2730,3940 3360,3940 v1(3420,3880)
WEBAR: U4.12 U7.192 | length 867.4
  Top Layer w8: U7.192@2246.98,3213.36 2246.98,3150.39 2293,3104.37 2293,2747 2300,2740 2300,2530 2275,2505 U4.12@2275,2378.27
pads on no net: J1.M1 J1.M2 J1.M3 J2.M1 J2.M2 J2.M3 J3.M1 J3.M2 J3.M3 J4.M1 J4.M2 J4.M3 J5.M1 J5.M2 J5.M3 JP2.1 JP3.1 U1.1 U1.14 U1.17 U1.21 U1.22 U1.23 U1.27 U1.30 U1.31 U1.44 U1.45 U1.46 U1.47 U1.48 U1.49 U1.50 U1.51 U1.53 U1.60 U1.64 U2.1 U2.14 U2.17 U2.21 U2.22 U2.23 U2.27 U2.30 U2.31 U2.44 U2.45 U2.46 U2.47 U2.48 U2.49 U2.50 U2.51 U2.53 U2.60 U2.64 U3.1 U3.34 U3.37 U3.43 U5.2 U5.9 U5.12 U5.13 U5.14 U5.15 U5.16 U7.3 U7.4 U7.5 U7.6 U7.7 U7.8 U7.15 U7.16 U7.17 U7.18 U7.20 U7.22 U7.23 U7.24 U7.27 U7.29 U7.56 U7.57 U7.58 U7.59 U7.64 U7.68 U7.69 U7.70 U7.82 U7.83 U7.84 U7.86 U7.87 U7.88 U7.89 U7.93 U7.94 U7.95 U7.96 U7.97 U7.98 U7.127 U7.129 U7.132 U7.133 U7.134 U7.135 U7.136 U7.138 U7.141 U7.145 U7.146 U7.147 U7.148 U7.149 U7.150 U7.151 U7.152 U7.154 U7.160 U7.161 U7.175 U7.204 U7.205 U7.206 U7.FID1 U7.FID2

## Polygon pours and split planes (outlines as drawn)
VCC3_3V on Top Layer "Top Layer-VCC3_3V" (solid, remove dead copper, pour order 1000): 23 vertices, not listed, extent 1905.67,2225.67 2344.33,2424.33
VCC3_3V on Top Layer "Top Layer-VCC3_3V 1" (solid, remove dead copper, pour order 1001): 25 vertices, not listed, extent 1969.67,2615.67 2231.33,2854.33
VCC3_3V on Top Layer "Top Layer-VCC3_3V 2" (solid, remove dead copper, pour order 1002): 19 vertices, not listed, extent 618.27,2405.67 884.33,2604.33
VCC3_3V on Top Layer "Top Layer-VCC3_3V 3" (solid, remove dead copper, pour order 1003): 2103.06,4533.06 2104.33,4530 2104.33,4360 2103.06,4356.94 2100,4355.67 2010.76,4355.67 2007.7,4356.94 2006.43,4360 2006.43,4447.44 1956.94,4496.94 1955.67,4500 1955.67,4530 1956.94,4533.06 1960,4534.33 2100,4534.33
VCC3_3V on Top Layer "Top Layer-VCC3_3V 4" (solid, remove dead copper, pour order 1004): 21 vertices, not listed, extent 2275.67,4345.67 2544.33,4604.33
VCC3_3V on Top Layer "Top Layer-VCC3_3V 5" (solid, remove dead copper, pour order 1005): 23 vertices, not listed, extent 2605.67,4005.67 2914.33,4194.33
VCC3_3V on Top Layer "Top Layer-VCC3_3V 6" (solid, remove dead copper, pour order 1006): 17 vertices, not listed, extent 2615.67,3665.67 2834.33,3814.33
VCC3_3V on Top Layer "Top Layer-VCC3_3V 7" (solid, remove dead copper, pour order 1007): 27 vertices, not listed, extent 2615.67,3295.67 2834.33,3558.24
VCC3_3V on Top Layer "Top Layer-VCC3_3V 8" (solid, remove dead copper, pour order 1008): 17 vertices, not listed, extent 2459.19,2925.67 2777.83,3254.33
VCC3_3V on Top Layer "Top Layer-VCC3_3V 9" (solid, remove dead copper, pour order 1009): 22 vertices, not listed, extent 2305.67,2925.67 2549.24,3254.33
VCC3_3V on Top Layer "Top Layer-VCC3_3V 10" (solid, remove dead copper, pour order 1010): 2103.06,3243.06 2104.33,3240 2104.33,3050 2103.06,3046.94 2100,3045.67 1974,3045.67 1970.94,3046.94 1969.67,3050 1969.67,3106.12 1970.94,3109.18 2026.12,3164.36 2026.12,3240 2027.39,3243.06 2030.45,3244.33 2100,3244.33
VCC3_3V on Top Layer "Top Layer-VCC3_3V 11" (solid, remove dead copper, pour order 1011): 25 vertices, not listed, extent 1685.67,2945.67 1844.33,3244.33
VCC3_3V on Top Layer "Top Layer-VCC3_3V 12" (solid, remove dead copper, pour order 1012): 20 vertices, not listed, extent 1285.67,3225.67 1504.33,3344.33
VCC3_3V on Top Layer "Top Layer-VCC3_3V 13" (solid, remove dead copper, pour order 1013): 1503.06,3576.66 1504.33,3573.6 1504.33,3357.06 1503.06,3354 1500,3352.73 1310.75,3352.73 1307.69,3354 1286.94,3374.75 1285.67,3377.82 1285.67,3480 1285.67,3573.6 1286.94,3576.66 1290,3577.93 1500,3577.93
VCC3_3V on Top Layer "Top Layer-VCC3_3V 14" (solid, remove dead copper, pour order 1014): 19 vertices, not listed, extent 1285.67,3645.67 1504.33,3840.33
VCC3_3V on Top Layer "Top Layer-VCC3_3V 15" (solid, remove dead copper, pour order 1015): 21 vertices, not listed, extent 1285.67,4245.67 1517.59,4454.33
VCC3_3V on Top Layer "Top Layer-VCC3_3V 16" (solid, remove dead copper, pour order 1016): 22 vertices, not listed, extent 1635.67,4345.67 1834.33,4634.33
VCC1_8V on Top Layer "Top Layer-VCC1_8V" (solid, remove dead copper, pour order 1017): 1923.06,4533.06 2013.83,4442.3 2015.09,4439.24 2015.09,4360 2013.83,4356.94 2010.76,4355.67 1830,4355.67 1826.94,4356.94 1825.67,4360 1825.67,4530 1826.94,4533.06 1830,4534.33 1920,4534.33
VCC1_8V on Top Layer "Top Layer-VCC1_8V 1" (solid, remove dead copper, pour order 1018): 2293.06,4533.06 2294.33,4530 2294.33,4360 2293.06,4356.94 2290,4355.67 2100,4355.67 2096.94,4356.94 2095.67,4360 2095.67,4530 2096.94,4533.06 2100,4534.33 2290,4534.33
VCC1_8V on Top Layer "Top Layer-VCC1_8V 2" (solid, remove dead copper, pour order 1019): 20 vertices, not listed, extent 2615.67,3982.65 2914.33,4074.33
VCC1_8V on Top Layer "Top Layer-VCC1_8V 3" (solid, remove dead copper, pour order 1020): 17 vertices, not listed, extent 2615.67,3805.67 2834.33,3894.33
VCC1_8V on Top Layer "Top Layer-VCC1_8V 4" (solid, remove dead copper, pour order 1021): 17 vertices, not listed, extent 2605.67,3505.67 2834.33,3604.33
VCC1_8V on Top Layer "Top Layer-VCC1_8V 5" (solid, remove dead copper, pour order 1022): 22 vertices, not listed, extent 2282.02,2925.67 2414.33,3244.33
VCC1_8V on Top Layer "Top Layer-VCC1_8V 6" (solid, remove dead copper, pour order 1023): 2153.06,3253.06 2154.33,3250 2154.33,3158.66 2174.01,3138.97 2175.28,3135.91 2175.28,3050 2174.01,3046.94 2170.95,3045.67 2110,3045.67 2106.94,3046.94 2105.67,3050 2105.67,3250 2106.94,3253.06 2110,3254.33 2150,3254.33
VCC1_8V on Top Layer "Top Layer-VCC1_8V 7" (solid, remove dead copper, pour order 1024): 22 vertices, not listed, extent 1785.67,2945.67 1877.3,3244.33
VCC1_8V on Top Layer "Top Layer-VCC1_8V 8" (solid, remove dead copper, pour order 1025): 1503.06,3653.06 1504.33,3650 1504.33,3570 1503.06,3566.94 1500,3565.67 1401.79,3565.67 1383.06,3546.94 1380,3545.67 1290,3545.67 1286.94,3546.94 1285.67,3550 1285.67,3650 1286.94,3653.06 1290,3654.33 1500,3654.33
VCC1_8V on Top Layer "Top Layer-VCC1_8V 9" (solid, remove dead copper, pour order 1026): 23 vertices, not listed, extent 1285.67,3745.67 1504.33,3911.7
VDDA_E on Top Layer "Top Layer-VDDA_E" (solid, remove dead copper, pour order 1027): 3723.06,1313.06 3724.33,1310 3724.33,1110 3723.06,1106.94 3683.06,1066.94 3680,1065.67 3580,1065.67 3576.94,1066.94 3575.67,1070 3575.67,1280 3576.94,1283.06 3606.94,1313.06 3610,1314.33 3720,1314.33
VDDA_E on Top Layer "Top Layer-VDDA_E 1" (solid, remove dead copper, pour order 1028): 36 vertices, not listed, extent 4121.18,1195.67 4504.33,1614.33
VDDA_E on Top Layer "Top Layer-VDDA_E 2" (solid, remove dead copper, pour order 1029): 26 vertices, not listed, extent 3845.67,1195.67 4034.33,1484.33
VDDA_E on Top Layer "Top Layer-VDDA_E 3" (solid, remove dead copper, pour order 1030): 23 vertices, not listed, extent 4025.67,1215.67 4214.33,1484.33
VDDD_E on Top Layer "Top Layer-VDDD_E" (solid, remove dead copper, pour order 1031): 43 vertices, not listed, extent 4255.67,1625.67 4584.33,2214.33
VDDD_E on Top Layer "Top Layer-VDDD_E 1" (solid, remove dead copper, pour order 1032): 18 vertices, not listed, extent 4025.67,1875.67 4160.58,2124.33
VDDD_E on Top Layer "Top Layer-VDDD_E 2" (solid, remove dead copper, pour order 1033): 23 vertices, not listed, extent 3495.67,1345.67 3864.33,1714.33
VDDD_B on Top Layer "Top Layer-VDDD_B" (solid, remove dead copper, pour order 1034): 17 vertices, not listed, extent 2227.75,855.67 2504.33,1064.33
VDDD_B on Top Layer "Top Layer-VDDD_B 1" (solid, remove dead copper, pour order 1035): 32 vertices, not listed, extent 2625.67,1295.67 2774.33,1514.33
VDDD_B on Top Layer "Top Layer-VDDD_B 2" (solid, remove dead copper, pour order 1036): 38 vertices, not listed, extent 2975.67,871.5 3294.33,1514.33
VDDD_B on Top Layer "Top Layer-VDDD_B 3" (solid, remove dead copper, pour order 1037): 3273.06,912.96 3274.33,909.9 3274.33,770 3273.06,766.94 3270,765.67 3050,765.67 3046.94,766.94 3045.67,770 3045.67,870 3046.94,873.06 3050,874.33 3174.03,874.33 3212.66,912.96 3215.72,914.23 3270,914.23
VDDA_B on Top Layer "Top Layer-VDDA_B" (solid, remove dead copper, pour order 1038): 47 vertices, not listed, extent 2882.13,305.67 3394.33,744.33
VDDA_A on Top Layer "Top Layer-VDDA_A" (solid, remove dead copper, pour order 1039): 19 vertices, not listed, extent 1175.67,505.67 1384.33,744.33
VDDA_B on Top Layer "Top Layer-VDDA_B 1" (solid, remove dead copper, pour order 1040): 22 vertices, not listed, extent 2819.14,505.67 3064.33,744.33
VDDA_B on Top Layer "Top Layer-VDDA_B 2" (solid, remove dead copper, pour order 1041): 19 vertices, not listed, extent 2555.67,505.67 2764.33,744.33
VDDD_A on Top Layer "Top Layer-VDDD_A" (solid, remove dead copper, pour order 1042): 1873.06,1123.06 1893.06,1103.06 1894.33,1100 1894.33,1060 1894.33,980 1894.33,880 1893.06,876.94 1890,875.67 1670,875.67 1666.94,876.94 1665.67,880 1665.67,1120 1666.94,1123.06 1670,1124.33 1870,1124.33
VDDD_A on Top Layer "Top Layer-VDDD_A 1" (solid, remove dead copper, pour order 1043): 17 vertices, not listed, extent 1665.67,765.67 1894.33,902.49
VDDD_A on Top Layer "Top Layer-VDDD_A 2" (solid, remove dead copper, pour order 1044): 17 vertices, not listed, extent 1615.67,1285.67 1894.33,1514.33
VDDD_A on Top Layer "Top Layer-VDDD_A 3" (solid, remove dead copper, pour order 1045): 19 vertices, not listed, extent 765.67,1685.67 1064.33,1924.33
VDDD_A on Top Layer "Top Layer-VDDD_A 4" (solid, remove dead copper, pour order 1046): 22 vertices, not listed, extent 1245.67,1285.67 1447.79,1514.33
VDDD_A on Top Layer "Top Layer-VDDD_A 5" (solid, remove dead copper, pour order 1047): 1123.06,1053.06 1124.33,1050 1124.33,930 1123.06,926.94 1120,925.67 880,925.67 876.94,926.94 856.94,946.94 855.67,950 855.67,1030 856.94,1033.06 876.94,1053.06 880,1054.33 1120,1054.33
VDDA_A on Top Layer "Top Layer-VDDA_A 1" (solid, remove dead copper, pour order 1048): 23 vertices, not listed, extent 835.67,925.67 1124.33,1054.33
VDDA_A on Top Layer "Top Layer-VDDA_A 2" (solid, remove dead copper, pour order 1049): 24 vertices, not listed, extent 1449.14,505.67 1684.33,744.33
VDDA_A on Top Layer "Top Layer-VDDA_A 3" (solid, remove dead copper, pour order 1050): 31 vertices, not listed, extent 1555.67,495.67 1894.33,744.33
VDDA_A on Top Layer "Top Layer-VDDA_A 4" (solid, remove dead copper, pour order 1051): 1043.06,563.06 1044.33,560 1044.33,310 1043.06,306.94 1040,305.67 750,305.67 746.94,306.94 745.67,310 745.67,560 746.94,563.06 750,564.33 1040,564.33
POS3_3V on Top Layer "Top Layer-POS3_3V" (solid, remove dead copper, pour order 1052): 714.65,2031.47 813.06,1933.06 814.33,1930 813.06,1926.94 764.33,1878.21 764.33,1690 763.06,1686.94 760,1685.67 643.18,1685.67 640.12,1686.94 638.85,1690 638.85,1960 640.12,1963.06 708.53,2031.47 711.59,2032.74
POS3_3V on Top Layer "Top Layer-POS3_3V 1" (solid, remove dead copper, pour order 1053): 753.06,563.06 754.33,560 754.33,310 753.06,306.94 750,305.67 660,305.67 656.94,306.94 636.94,326.94 635.67,330 635.67,540 636.94,543.06 656.94,563.06 660,564.33 750,564.33
POS3_3V on Top Layer "Top Layer-POS3_3V 2" (solid, remove dead copper, pour order 1054): 3543.06,293.06 3544.33,290 3544.33,180 3543.06,176.94 3523.06,156.94 3520,155.67 3340,155.67 3336.94,156.94 3316.94,176.94 3315.67,180 3315.67,290 3316.94,293.06 3320,294.33 3540,294.33
POS3_3V on Top Layer "Top Layer-POS3_3V 3" (solid, remove dead copper, pour order 1055): 20 vertices, not listed, extent 3435.67,835.67 3574.33,1134.33
VCC1_8V on Top Layer "Top Layer-VCC1_8V 10" (solid, remove dead copper, pour order 1056): 28 vertices, not listed, extent 2698.37,2865.67 2934.33,3264.33
VCC1_8V on Top Layer "Top Layer-VCC1_8V 11" (solid, remove dead copper, pour order 1057): 20 vertices, not listed, extent 1265.67,3905.67 1504.33,4034.33
VCC3_3V on Top Layer "Top Layer-VCC3_3V 17" (solid, remove dead copper, pour order 1058): 19 vertices, not listed, extent 1265.67,4041.71 1504.33,4134.33
VCC3_3V on Top Layer "Top Layer-VCC3_3V 18" (solid, remove dead copper, pour order 1059): 2793.06,4533.06 2794.33,4530 2794.33,4400 2793.06,4396.94 2753.06,4356.94 2750,4355.67 2550,4355.67 2546.94,4356.94 2545.67,4360 2545.67,4530 2546.94,4533.06 2550,4534.33 2790,4534.33
POS5V on Top Layer "Top Layer-POS5V" (solid, remove dead copper, pour order 1060): 26 vertices, not listed, extent 3495.67,3815.67 3724.33,4074.33
PWR_IN on Top Layer "Top Layer-PWR_IN" (solid, remove dead copper, pour order 1061): 18 vertices, not listed, extent 3905.67,4065.67 4314.33,4304.33
NetC96_1 on Top Layer "Top Layer-NetC96_1" (solid, remove dead copper, pour order 1062): 33 vertices, not listed, extent 3585.67,3845.42 4594.33,4224.33
POS1_8V on Top Layer "Top Layer-POS1_8V" (solid, remove dead copper, pour order 1063): 17 vertices, not listed, extent 4085.67,3415.67 4594.33,3834.33
NetC79_1 on Top Layer "Top Layer-NetC79_1" (solid, remove dead copper, pour order 1064): 21 vertices, not listed, extent 3765.67,2725.67 4594.33,3044.33
POS1_8V on Top Layer "Top Layer-POS1_8V 1" (solid, remove dead copper, pour order 1065): 3063.06,2933.06 3064.33,2930 3064.33,2790 3063.06,2786.94 2943.06,2666.94 2940,2665.67 2936.94,2666.94 2906.94,2696.94 2905.67,2700 2905.67,2800 2905.67,2930 2906.94,2933.06 2910,2934.33 3060,2934.33
POS5V on Top Layer "Top Layer-POS5V 1" (solid, remove dead copper, pour order 1066): 3753.06,3113.06 3754.33,3110 3754.33,2830 3753.06,2826.94 3750,2825.67 3620,2825.67 3616.94,2826.94 3576.94,2866.94 3575.67,2870 3575.67,3080 3576.94,3083.06 3606.94,3113.06 3610,3114.33 3750,3114.33
VCC3_3V on Top Layer "Top Layer-VCC3_3V 19" (solid, remove dead copper, pour order 1067): 3513.06,3073.06 3533.06,3053.06 3534.33,3050 3534.33,2420 3534.33,2370 3533.06,2366.94 3530,2365.67 3390,2365.67 3386.94,2366.94 3385.67,2370 3385.67,3070 3386.94,3073.06 3390,3074.33 3510,3074.33
POS3_3V on Top Layer "Top Layer-POS3_3V 4" (solid, remove dead copper, pour order 1068): 3333.06,1733.06 3443.06,1623.06 3444.33,1620 3444.33,1530 3443.06,1526.94 3440,1525.67 3210,1525.67 3206.94,1526.94 3205.67,1530 3205.67,1620 3206.94,1623.06 3210,1624.33 3218.21,1624.33 3326.94,1733.06 3330,1734.33
POS3_3V on Top Layer "Top Layer-POS3_3V 5" (solid, remove dead copper, pour order 1069): 29 vertices, not listed, extent 3545.67,2155.67 4594.33,2864.33
POS3_3V on Top Layer "Top Layer-POS3_3V 6" (solid, remove dead copper, pour order 1070): 25 vertices, not listed, extent 3755.67,3085.67 4194.33,3214.33
GND on Top Layer "Top Layer-GND" (solid, remove dead copper, pour order 1071): 4673.06,4673.06 4674.33,4670 4674.33,50 4673.06,46.94 4670,45.67 50,45.67 46.94,46.94 45.67,50 45.67,4670 46.94,4673.06 50,4674.33 4670,4674.33
VCC3_3V on MidLayer1 "MidLayer1-VCC3_3V" (solid, remove dead copper, pour order 1072): 60 vertices, not listed, extent 655.67,2215.67 3574.33,4634.33
POS3_3V on MidLayer1 "MidLayer1-POS3_3V" (solid, remove dead copper, pour order 1073): 82 vertices, not listed, extent 195.67,155.67 4574.33,3944.33
VDDD_A on MidLayer1 "MidLayer1-VDDD_A" (solid, remove dead copper, pour order 1074): 19 vertices, not listed, extent 795.67,775.67 1904.33,1944.33
VDDA_A on MidLayer1 "MidLayer1-VDDA_A" (solid, remove dead copper, pour order 1075): 23 vertices, not listed, extent 791.67,455.67 1844.33,664.33
VDDA_B on MidLayer1 "MidLayer1-VDDA_B" (solid, remove dead copper, pour order 1076): 20 vertices, not listed, extent 2635.67,395.67 3264.33,664.33
VDDD_B on MidLayer1 "MidLayer1-VDDD_B" (solid, remove dead copper, pour order 1077): 19 vertices, not listed, extent 2235.67,775.67 3304.33,1504.33
VDDA_E on MidLayer1 "MidLayer1-VDDA_E" (solid, remove dead copper, pour order 1078): 19 vertices, not listed, extent 3555.67,1135.67 4504.33,1504.33
VDDD_E on MidLayer1 "MidLayer1-VDDD_E" (solid, remove dead copper, pour order 1079): 18 vertices, not listed, extent 3555.67,1515.67 4444.33,2144.33
VCC1_8V on MidLayer1 "MidLayer1-VCC1_8V" (solid, remove dead copper, pour order 1080): 27 vertices, not listed, extent 1455.67,3075.67 2944.33,4364.33
POS5V on MidLayer1 "MidLayer1-POS5V" (solid, remove dead copper, pour order 1081): 22 vertices, not listed, extent 3205.67,2815.67 3884.33,4644.33
GND on MidLayer1 "MidLayer1-GND" (solid, remove dead copper, pour order 1082): 4673.06,4673.06 4674.33,4670 4674.33,50 4673.06,46.94 4670,45.67 50,45.67 46.94,46.94 45.67,50 45.67,4670 46.94,4673.06 50,4674.33 4670,4674.33
GND on Bottom Layer "Bottom Layer-GND" (solid, remove dead copper, pour order 1083): 4673.06,4673.06 4674.33,4670 4674.33,50 4673.06,46.94 4670,45.67 50,45.67 46.94,46.94 45.67,50 45.67,4670 46.94,4673.06 50,4674.33 4670,4674.33
POS1_8V on Bottom Layer "Bottom Layer-POS1_8V" (solid, remove dead copper, pour order 1084): 25 vertices, not listed, extent 2735.67,2645.67 4584.33,3864.33
PWR_IN on Bottom Layer "Bottom Layer-PWR_IN" (solid, remove dead copper, pour order 1085): 18 vertices, not listed, extent 3435.67,3995.67 4224.33,4564.33
GND on Ground (split plane): 4704.31,20.1 20.1,20.1 20.1,4704.31 4704.31,4704.31

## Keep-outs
Keep-Out Layer:
  lines w11.81: 51.18,51.18 4673.23,51.18 4673.23,4673.23 51.18,4673.23 51.18,51.18

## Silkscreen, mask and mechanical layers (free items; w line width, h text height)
Top Overlay:
  lines w8: 4190,1135.43 4190,1180
  lines w10: 1560,4640 1730,4640 ; 1710,4620 1730,4640 ; 1710,4660 1730,4640
  text "Altium" at 750,3120 h80
  text "Video" at 750,2990 h80
  text "Multiplexer" at 750,2860 h80
  text "PCB Rev B" at 3580,704 h50
  text "16-Jan-2004" at 3580,608 h50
